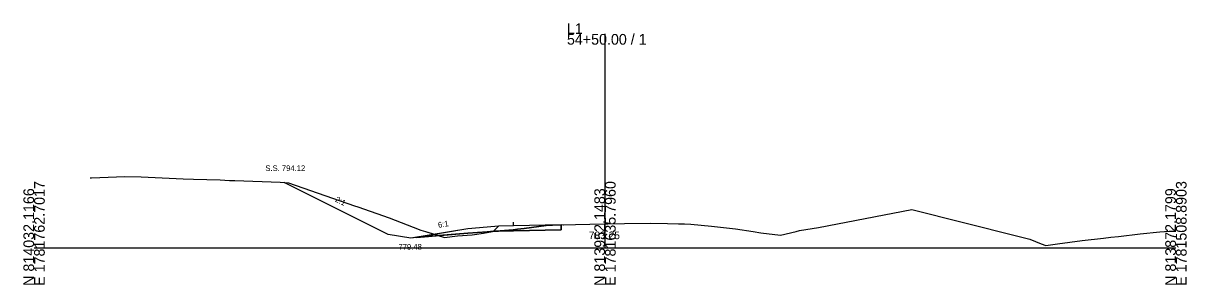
# Model space of a CAD drawing. Extents: x 5574 to 10203, y -10 to 9546.
# Drawn here: x 6597.2 to 6902.8, y 1490.3 to 1558.9 of the extents above; entities that cross this region are included whole.
import ezdxf

# ---------------------------------------------------------------- set-up
doc = ezdxf.new("R2010")
doc.units = 0
for name, color, linetype in [('Exist Cross Section Cell', 7, 'Continuous'), ('Exist XS Center Line Elevation Label', 7, 'Continuous'), ('Exist XS Ground Line', 7, 'Continuous'), ('Prop XS Ditch Slope Text', 7, 'Continuous'), ('Prop XS Ditch Standard Text', 7, 'Continuous'), ('Prop XS Dump Level', 7, 'Continuous'), ('Prop XS Earthwork Shape', 7, 'Continuous'), ('Prop XS EOT Tick Mark', 7, 'Continuous'), ('Prop XS Finish Grade', 7, 'Continuous'), ('Prop XS Finish Grade Earthwork', 7, 'Continuous'), ('Prop XS Finish Grade Paved Shoulder', 7, 'Continuous'), ('Prop XS Finish Grade Pavement', 7, 'Continuous'), ('Prop XS Hydro Typical Ditch Data', 7, 'Continuous'), ('Prop XS Pvmt Edge Slope', 7, 'Continuous'), ('Prop XS Side Slope Text', 7, 'Continuous'), ('Prop XS SS Elevation Text', 7, 'Continuous'), ('Prop XS Subgrade Earthwork', 7, 'Continuous'), ('Scratch_Level_3', 7, 'Continuous'), ('Scratch_Level_6', 7, 'Continuous')]:
    doc.layers.add(name, color=color, linetype=linetype)

msp = doc.modelspace()

# ---------------------------------------------------------------- linework, layer by layer
at = {"layer": 'Exist Cross Section Cell'}
for p, q in [((6750, 1500), (6750, 1556.07)), ((6600, 1500), (6750, 1500)), ((6750, 1500), (6900, 1500))]:
    msp.add_line(p, q, dxfattribs=at)
at = {"layer": 'Exist XS Ground Line'}
for p, q in [((6614.76, 1518.34), (6615.09, 1518.37)), ((6615.09, 1518.37), (6623.8, 1518.69)), ((6623.8, 1518.69), (6628.15, 1518.6)), ((6628.15, 1518.6), (6639.17, 1518.07)), ((6639.17, 1518.07), (6641.9, 1518.01)), ((6641.9, 1518.01), (6648.85, 1517.77)), ((6648.85, 1517.77), (6651.33, 1517.68)), ((6651.33, 1517.68), (6652.74, 1517.63)), ((6652.74, 1517.63), (6664.63, 1517.23)), ((6664.63, 1517.23), (6666.86, 1517)), ((6666.86, 1517), (6672.65, 1514.99)), ((6672.65, 1514.99), (6684.16, 1511.01)), ((6684.16, 1511.01), (6685.08, 1510.7)), ((6685.08, 1510.7), (6693.27, 1507.85)), ((6693.27, 1507.85), (6699.59, 1505.36)), ((6806.1, 1505.33), (6830.59, 1510.03)), ((6830.59, 1510.03), (6858.13, 1503.16)), ((6699.59, 1505.36), (6701.57, 1504.63)), ((6701.57, 1504.63), (6702.82, 1504.28)), ((6702.82, 1504.28), (6707.87, 1502.71)), ((6718.08, 1503.83), (6720.98, 1504.33)), ((6720.98, 1504.33), (6725.87, 1504.74)), ((6725.87, 1504.74), (6727.05, 1504.85)), ((6727.05, 1504.85), (6728.79, 1505.06)), ((6728.79, 1505.06), (6734.52, 1505.8)), ((6734.52, 1505.8), (6736.19, 1505.88)), ((6736.19, 1505.88), (6738.49, 1505.99)), ((6738.49, 1505.99), (6746.02, 1506.16)), ((6746.02, 1506.16), (6750, 1506.25)), ((6750, 1506.25), (6750.75, 1506.27)), ((6750.75, 1506.27), (6755.11, 1506.33)), ((6755.11, 1506.33), (6762.06, 1506.42)), ((6762.06, 1506.42), (6766.41, 1506.33)), ((6766.41, 1506.33), (6769.32, 1506.28)), ((6769.32, 1506.28), (6770.85, 1506.23)), ((6770.85, 1506.23), (6772.54, 1506.18)), ((6772.54, 1506.18), (6777.94, 1505.64)), ((6777.94, 1505.64), (6784.32, 1504.98)), ((6784.32, 1504.98), (6788.9, 1504.22)), ((6788.9, 1504.22), (6790.96, 1503.92)), ((6796.14, 1503.27), (6800.21, 1504.27)), ((6800.21, 1504.27), (6801.14, 1504.55)), ((6801.14, 1504.55), (6806.1, 1505.33)), ((6890.57, 1503.68), (6895.79, 1504.19)), ((6895.79, 1504.19), (6898.19, 1504.31)), ((6898.19, 1504.31), (6899.56, 1504.37)), ((6899.56, 1504.37), (6900, 1504.37)), ((6707.87, 1502.71), (6711.21, 1503.09)), ((6711.21, 1503.09), (6715.11, 1503.4)), ((6715.11, 1503.4), (6718.08, 1503.83)), ((6790.96, 1503.92), (6796.14, 1503.27)), ((6858.13, 1503.16), (6861.63, 1502.21)), ((6861.63, 1502.21), (6864.63, 1501.01)), ((6864.63, 1501.01), (6865.82, 1500.56)), ((6865.82, 1500.56), (6868.86, 1500.99)), ((6868.86, 1500.99), (6875.35, 1501.89)), ((6875.35, 1501.89), (6880.94, 1502.52)), ((6880.94, 1502.52), (6882.88, 1502.74)), ((6882.88, 1502.74), (6884.88, 1502.96)), ((6884.88, 1502.96), (6890.57, 1503.68))]:
    msp.add_line(p, q, dxfattribs=at)
at = {"layer": 'Prop XS Dump Level'}
msp.add_line((6738.48, 1506.02), (6726, 1505.77), dxfattribs=at)
msp.add_line((6738.48, 1506.02), (6726, 1505.77), dxfattribs=at)
at = {"layer": 'Prop XS Earthwork Shape'}
for points in [[(6700.43, 1502.72), (6699, 1502.48), (6693, 1503.48), (6665.72, 1517.12), (6666.86, 1517), (6672.65, 1514.99), (6684.16, 1511.01), (6685.08, 1510.7), (6693.27, 1507.85), (6699.59, 1505.36), (6701.57, 1504.63), (6702.82, 1504.28), (6706.31, 1503.19)], [(6714, 1503.81), (6706.31, 1503.19), (6707.87, 1502.71), (6711.21, 1503.09), (6715.11, 1503.4), (6718.08, 1503.83), (6720.98, 1504.33), (6721.28, 1504.36), (6720.72, 1504.34), (6719, 1504.21)], [(6738.49, 1504.74), (6738.49, 1505.99), (6736.19, 1505.88), (6734.52, 1505.8), (6728.79, 1505.06), (6727.05, 1504.85), (6725.87, 1504.74), (6721.28, 1504.36), (6722, 1504.37), (6726, 1504.46)]]:
    msp.add_lwpolyline(points, close=True, dxfattribs=at)
at = {"layer": 'Prop XS EOT Tick Mark'}
msp.add_line((6726, 1505.71), (6726, 1506.71), dxfattribs=at)
at = {"layer": 'Prop XS Finish Grade'}
for p, q in [((6714, 1504.98), (6700.43, 1502.72)), ((6719, 1505.38), (6714, 1504.98)), ((6722, 1505.62), (6719, 1505.38))]:
    msp.add_line(p, q, dxfattribs=at)
at = {"layer": 'Prop XS Finish Grade Earthwork'}
for p, q in [((6693, 1503.48), (6665.72, 1517.12)), ((6699, 1502.48), (6693, 1503.48)), ((6700.43, 1502.72), (6699, 1502.48))]:
    msp.add_line(p, q, dxfattribs=at)
at = {"layer": 'Prop XS Finish Grade Paved Shoulder'}
msp.add_line((6726, 1505.71), (6722, 1505.62), dxfattribs=at)
at = {"layer": 'Prop XS Finish Grade Pavement'}
msp.add_line((6738.49, 1505.99), (6726, 1505.71), dxfattribs=at)
at = {"layer": 'Prop XS Hydro Typical Ditch Data'}
for p, q in [((6693, 1503.48), (6665.72, 1517.12)), ((6714, 1504.98), (6699, 1502.48)), ((6699, 1502.48), (6693, 1503.48))]:
    msp.add_line(p, q, dxfattribs=at)
at = {"layer": 'Prop XS Pvmt Edge Slope'}
msp.add_line((6722, 1505.62), (6720.72, 1504.34), dxfattribs=at)
at = {"layer": 'Prop XS Subgrade Earthwork'}
for p, q in [((6719, 1504.21), (6714, 1503.81)), ((6720.72, 1504.34), (6719, 1504.21)), ((6722, 1504.37), (6720.72, 1504.34)), ((6726, 1504.46), (6722, 1504.37)), ((6738.49, 1504.74), (6726, 1504.46)), ((6738.49, 1504.74), (6738.49, 1505.99)), ((6714, 1503.81), (6700.43, 1502.72))]:
    msp.add_line(p, q, dxfattribs=at)
at = {"layer": 'Scratch_Level_3'}
for p, q in [((6714, 1504.98), (6700.43, 1502.72)), ((6719, 1505.38), (6714, 1504.98)), ((6714, 1503.81), (6719, 1504.21)), ((6722, 1505.62), (6719, 1505.38)), ((6719, 1504.21), (6720.72, 1504.34)), ((6720.72, 1504.34), (6722, 1505.62)), ((6700.43, 1502.72), (6714, 1503.81))]:
    msp.add_line(p, q, dxfattribs=at)
at = {"layer": 'Scratch_Level_6'}
for points in [[(6722, 1504.37), (6721.28, 1504.36), (6725.87, 1504.74), (6727.05, 1504.85), (6728.79, 1505.06), (6734.52, 1505.8), (6736.19, 1505.88), (6738.49, 1505.99), (6738.49, 1504.74), (6726, 1504.46)], [(6705.25, 1503.52), (6706.31, 1503.19), (6700.43, 1502.72)]]:
    msp.add_lwpolyline(points, close=True, dxfattribs=at)

# ---------------------------------------------------------------- texts
at = {"layer": 'Exist Cross Section Cell'}
for s, p in [('54+50.00 / 1', (6740, 1553.27)), ('L1', (6740, 1556.07))]:
    msp.add_text(s, height=2.8, dxfattribs=at).set_placement(p)
for s, p in [('E 1781762.7017', (6602.8, 1490)), ('E 1781635.7960', (6752.8, 1490)), ('E 1781508.8903', (6902.8, 1490)), ('N 814032.1166', (6600, 1490)), ('N 813952.1483', (6750, 1490)), ('N 813872.1799', (6900, 1490))]:
    msp.add_text(s, height=2.8, rotation=90, dxfattribs=at).set_placement(p)
at = {"layer": 'Exist XS Center Line Elevation Label'}
msp.add_text('783.25', height=2, dxfattribs=at).set_placement((6745.74, 1502.25))
at = {"layer": 'Prop XS Ditch Slope Text'}
msp.add_text('6:1', height=1.5, rotation=9.4623, dxfattribs=at).set_placement((6706.25, 1505.21))
at = {"layer": 'Prop XS Ditch Standard Text'}
msp.add_text('779.48', height=1.5, dxfattribs=at).set_placement((6695.74, 1499.48))
at = {"layer": 'Prop XS Dump Level'}
for s, height, p in [('Case4', 0.04, (6714, 1504.94)), ('Eop', 0.3, (6738.49, 1505.69))]:
    msp.add_text(s, height=height, dxfattribs=at).set_placement(p)
at = {"layer": 'Prop XS Side Slope Text'}
msp.add_text('2:1', height=1.5, rotation=333.4349, dxfattribs=at).set_placement((6678.95, 1512.19))
at = {"layer": 'Prop XS SS Elevation Text'}
msp.add_text('S.S. 794.12', height=1.5, dxfattribs=at).set_placement((6660.76, 1520.12))

doc.saveas('drawing.dxf')
